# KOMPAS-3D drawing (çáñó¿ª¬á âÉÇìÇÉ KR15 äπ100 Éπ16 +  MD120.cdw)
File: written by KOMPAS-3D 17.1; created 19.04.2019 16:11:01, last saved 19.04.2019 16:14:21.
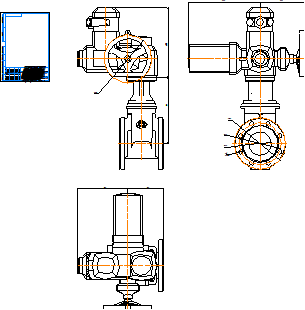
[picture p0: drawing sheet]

Sheet 1: A4, portrait

Title block, sheet 1: name: Задвижка ГРАНАР KR15 Ду100 Ру16 + / MD120; material: Внимание! Данный продукт является объектом авторского права ООО «Торговый Дом АДЛ». / Запрещается изменение, копирование, распространение / (в том числе путем копирования на другие сайты и ресурсы в Интернете) / или любое иное использование информации и объектов без предварительного / согласия правообладателя (ООО «Торговый Дом АДЛ»).; mass: 111,84; sheets: 1; organisation: ООО "Торговый дом АДЛ"; sheet format: A4

Views: Вид 1, Проекционный вид 2, Проекционный вид 3
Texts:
  user
Dimensions and other numbers on the sheet: 282; 299; 205; 220; 180; 100; 19; 8 Отв.; 308; 187; 214; 153; 1:1; 1; 111,84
